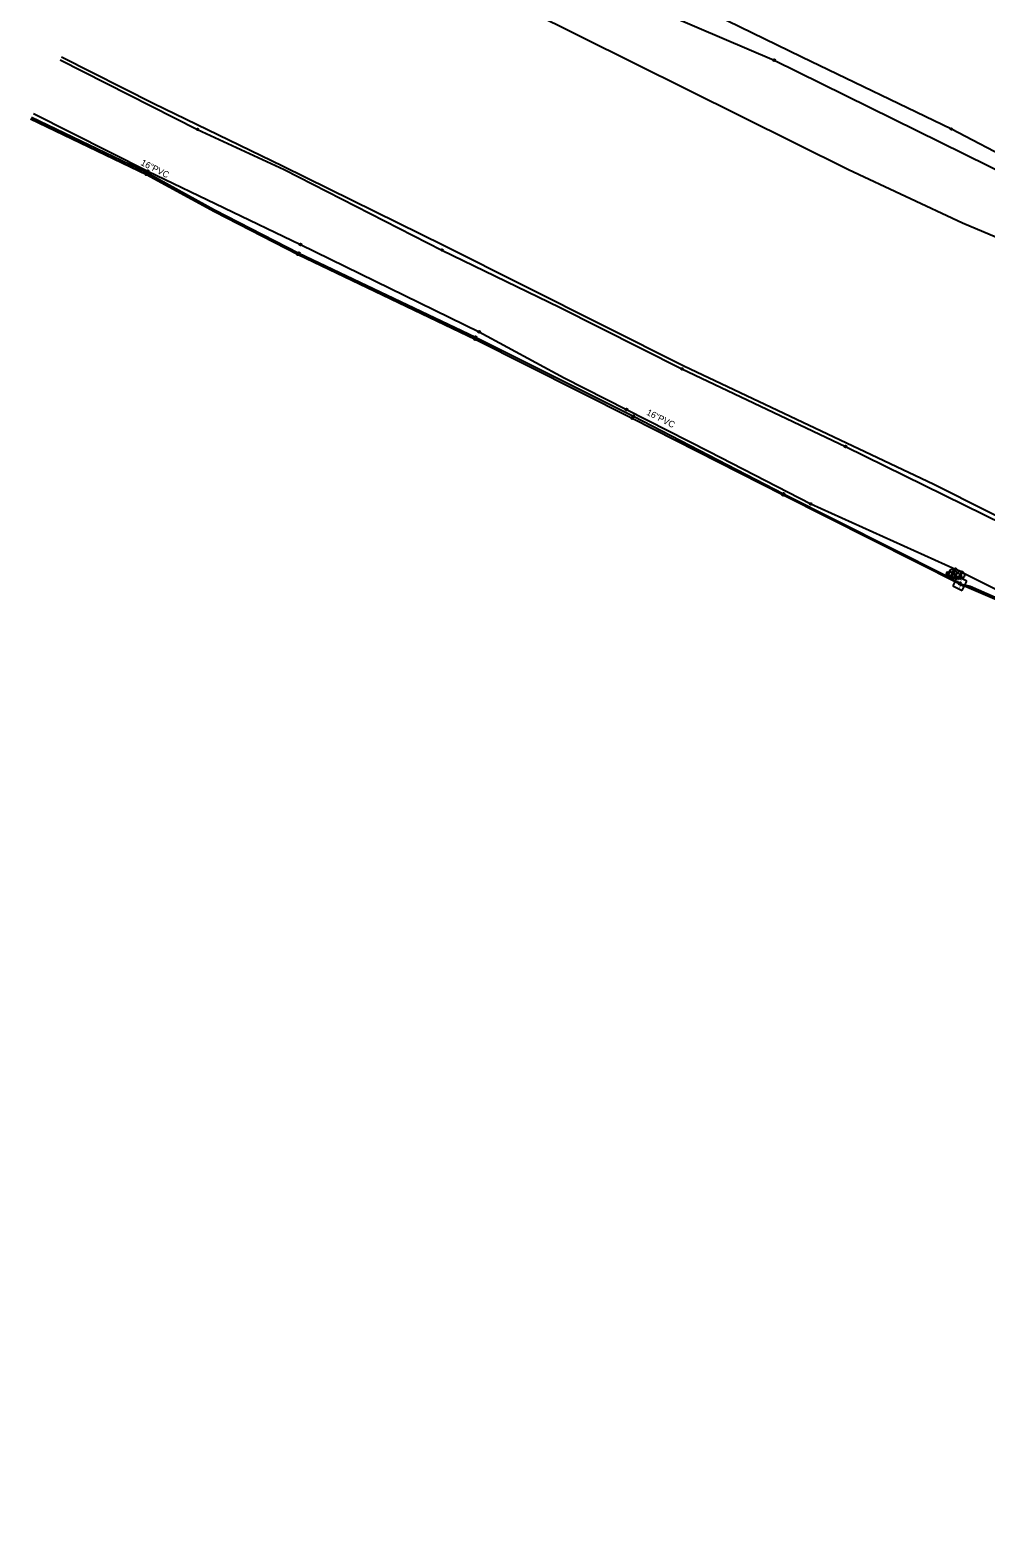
# Model space of a CAD drawing. Extents: x 2244485 to 2250986, y 199568 to 203007.
# Drawn here: x 2248328 to 2248849, y 200055 to 200876 of the extents above; entities that cross this region are included whole.
import ezdxf

# ---------------------------------------------------------------- set-up
doc = ezdxf.new("R2010")
doc.units = 0
for name, color, linetype in [('Default', 7, 'Continuous'), ('Exist Utilities Sanitary Sewer Forced Main SUE LOS B', 7, 'Continuous'), ('Exist Utilities Telephone Hand Hole CELL', 7, 'Continuous'), ('Exist Utilities Telephone UG Cable SUE LOS C', 7, 'Continuous'), ('Exist Utilities Telephone UG FO SUE LOS B', 7, 'Continuous'), ('Exist Utilities Telephone UG FO SUE LOS C', 7, 'Continuous'), ('Exist Utilities Water Fire Hydrant CELL', 7, 'Continuous'), ('Exist Utilities Water UG Line SUE LOS B', 7, 'Continuous'), ('Exist Utilities Water UG Line SUE LOS B Text', 7, 'Continuous'), ('Exist Utilities Water Valve CELL', 7, 'Continuous')]:
    doc.layers.add(name, color=color, linetype=linetype)

# ---------------------------------------------------------------- blocks, each defined once
blk = doc.blocks.new('SurveyPointCell')
at = {"layer": 'Default'}
for p, q in [((-0.5, 0), (0.5, 0)), ((0, -0.5), (0, 0.5))]:
    blk.add_line(p, q, dxfattribs=at)
blk.add_circle((0, 0), 0.5, dxfattribs=at)

msp = doc.modelspace()

# ---------------------------------------------------------------- linework, layer by layer
at = {"layer": 'Exist Utilities Sanitary Sewer Forced Main SUE LOS B'}
msp.add_lwpolyline([(2247735.41, 201350.67), (2247801.59, 201317.51), (2247922.39, 201259.82), (2248074.17, 201183.48), (2248161.38, 201141.9), (2248228.53, 201112.29), (2248334.87, 201058.12), (2248487.25, 200983.06), (2248649.22, 200895.6), (2248733.43, 200859.57), (2248875.85, 200789.39), (2249055.92, 200697.85), (2249217.76, 200621.23), (2249370.62, 200544.89)], dxfattribs=at)
at = {"layer": 'Exist Utilities Telephone Hand Hole CELL'}
for p, q in [((2248833.24, 200578.53), (2248830.61, 200573.44)), ((2248830.61, 200573.44), (2248835.7, 200570.82)), ((2248838.33, 200575.9), (2248833.24, 200578.53)), ((2248834.47, 200574.67), (2248834.47, 200574.67)), ((2248835.7, 200570.82), (2248838.33, 200575.9))]:
    msp.add_line(p, q, dxfattribs=at)
at = {"layer": 'Exist Utilities Telephone UG Cable SUE LOS C'}
msp.add_lwpolyline([(2248238.7, 201066.28), (2248423.59, 200974.24), (2248773.82, 200799.99), (2248835.88, 200770.97), (2248854.39, 200763.25), (2248860.78, 200766.45), (2248866.15, 200773.75), (2248880.19, 200799.94), (2248868.48, 200773.69), (2248865.46, 200766.31), (2248865.37, 200759.63), (2248891.36, 200747.54), (2249235.17, 200571.04), (2249362.52, 200506.1), (2249646.99, 200363.79)], dxfattribs=at)
at = {"layer": 'Exist Utilities Telephone UG FO SUE LOS B'}
for points in [[(2247734.6, 201364.13), (2247798.15, 201331.66), (2247859.88, 201301.14), (2247925.6, 201269.67), (2247988.72, 201238.28), (2248114.06, 201176.6), (2248183.16, 201141.53), (2248221.91, 201121.81), (2248290.07, 201088.12), (2248488.94, 200988.89), (2248609.32, 200928.77), (2248687.7, 200891.02), (2248748.44, 200861.37), (2248829.89, 200822.11), (2248864.68, 200804.04), (2248883.46, 200794.42), (2248944.92, 200764.27), (2249005.82, 200733.82), (2249066.5, 200704.1), (2249128.64, 200672.91), (2249190.46, 200641.51), (2249254.14, 200610.49), (2249321.49, 200578.44), (2249387.5, 200544.86)], [(2248344.53, 200859.83), (2248419.29, 200821.92), (2248466.62, 200800.01), (2248552.5, 200756.23), (2248616.5, 200725.07), (2248683.2, 200691.48), (2248772.25, 200649.25), (2248879.65, 200596.48), (2248899.78, 200585.98), (2248912.71, 200576.87), (2248936.09, 200565.52), (2248980.22, 200544.6), (2249032.26, 200518.49), (2249090.09, 200489.91), (2249149.46, 200460.97), (2249211.92, 200430.6), (2249266.25, 200404.93), (2249319.08, 200376.82), (2249375.45, 200350.06)], [(2248328.4, 200827.57), (2248391.63, 200797.41), (2248428.53, 200777.25), (2248474.15, 200753.86), (2248570.53, 200707.71), (2248656.14, 200664.65), (2248738.24, 200622.89), (2248834.42, 200574.52)], [(2248328.89, 200828.55), (2248391.84, 200798.46), (2248428.67, 200778.04), (2248474.62, 200754.59), (2248570.71, 200708.84), (2248656.71, 200665.82), (2248738.57, 200623.53), (2248826.46, 200579.25), (2248834.42, 200574.52)], [(2248834.42, 200574.52), (2248877.75, 200555.98), (2248921.13, 200534.6), (2249032.64, 200482.8), (2249142.58, 200428.84), (2249188.38, 200405.49), (2249254.87, 200369.28), (2249313.69, 200339.47), (2249478.6, 200256.38)], [(2248834.42, 200574.52), (2248840.11, 200573.18), (2248878.1, 200556.55), (2248921.45, 200535.34), (2249032.65, 200483.49), (2249143.05, 200429.5), (2249188.93, 200406.33), (2249255.33, 200370.44), (2249314.07, 200340.07), (2249478.96, 200257.14)]]:
    msp.add_lwpolyline(points, dxfattribs=at)
at = {"layer": 'Exist Utilities Telephone UG FO SUE LOS C'}
msp.add_lwpolyline([(2248345.35, 200861.45), (2248395.63, 200836.07), (2248465.71, 200802.05), (2248553.74, 200758.66), (2248684.23, 200693.17), (2248820.3, 200628.68), (2248908.04, 200584.64), (2248916.96, 200578.87), (2248981.98, 200546.97), (2249120.09, 200477.99), (2249226.44, 200426.02), (2249266.92, 200406.38), (2249295.86, 200391.44), (2249352.73, 200362.96), (2249442.05, 200319.48)], dxfattribs=at)
at = {"layer": 'Exist Utilities Water Fire Hydrant CELL'}
msp.add_line((2248830.17, 200578.94), (2248830.17, 200578.94), dxfattribs=at)
for points in [[(2248828.69, 200580.25), (2248827.53, 200580.82), (2248827.08, 200579.9), (2248828.26, 200579.32)], [(2248831.48, 200580.43), (2248832.05, 200581.58), (2248831.13, 200582.04), (2248830.56, 200580.88)], [(2248832.12, 200578.55), (2248833.27, 200577.98), (2248832.82, 200577.07), (2248831.64, 200577.65)]]:
    msp.add_lwpolyline(points, dxfattribs=at)
for radius in [1.98, 0.243]:
    msp.add_circle((2248830.17, 200578.94), radius, dxfattribs=at)
at = {"layer": 'Exist Utilities Water UG Line SUE LOS B'}
msp.add_line((2248832.07, 200582.49), (2248832.07, 200582.49), dxfattribs=at)
for points in [[(2248329.97, 200830.62), (2248392.26, 200799.22), (2248475.47, 200759.22), (2248572.73, 200711.68), (2248619.08, 200686.69), (2248652.95, 200669.4), (2248697.99, 200646.48), (2248753.28, 200617.97), (2248832.07, 200582.49)], [(2248832.07, 200582.49), (2248830.75, 200580.22), (2248830.17, 200578.94)], [(2248835.51, 200580.83), (2248832.07, 200582.49)], [(2248834.8, 200579.26), (2248835.51, 200580.83)], [(2248835.51, 200580.83), (2248922.65, 200537.42), (2249033.15, 200484.25), (2249189.81, 200407.98), (2249240.08, 200380.66), (2249481.52, 200258.57), (2249600.85, 200198.31), (2249670.02, 200162.8), (2249862.82, 200069.86), (2249895.12, 200055.15)]]:
    msp.add_lwpolyline(points, dxfattribs=at)
at = {"layer": 'Exist Utilities Water Valve CELL'}
for points in [[(2248832.2, 200581.82), (2248829.05, 200578.67), (2248830.62, 200580.24), (2248832.2, 200578.67), (2248829.05, 200581.82)], [(2248836.36, 200580.8), (2248833.21, 200577.65), (2248834.78, 200579.22), (2248836.36, 200577.65), (2248833.21, 200580.8)]]:
    msp.add_lwpolyline(points, dxfattribs=at)
for centre in [(2248830.62, 200580.24), (2248834.78, 200579.22)]:
    msp.add_circle(centre, 2.23, dxfattribs=at)

# ---------------------------------------------------------------- block references
at = {"layer": 'Default'}
for p in [(2248733.43, 200859.57), (2248419.29, 200821.92), (2248829.89, 200822.11), (2248391.63, 200797.41), (2248391.84, 200798.46), (2248392.26, 200799.22), (2248474.15, 200753.86), (2248474.62, 200754.59), (2248475.47, 200759.22), (2248552.5, 200756.23), (2248572.73, 200711.68), (2248570.53, 200707.71), (2248570.71, 200708.84), (2248683.2, 200691.48), (2248652.95, 200669.4), (2248656.14, 200664.65), (2248656.71, 200665.82), (2248772.25, 200649.25), (2248738.24, 200622.89), (2248738.57, 200623.53), (2248753.28, 200617.97), (2248830.75, 200580.22), (2248832.07, 200582.49), (2248832.07, 200582.49), (2248835.51, 200580.83), (2248835.51, 200580.83), (2248830.17, 200578.94), (2248834.42, 200574.52), (2248834.54, 200574.68), (2248834.67, 200574.71), (2248834.68, 200574.7), (2248834.8, 200579.26)]:
    msp.add_blockref('SurveyPointCell', p, dxfattribs=at)

# ---------------------------------------------------------------- texts
at = {"layer": 'Exist Utilities Telephone Hand Hole CELL'}
for p in [(2248832.35, 200575.1), (2248833.96, 200572.62)]:
    msp.add_text('H', height=2.5, rotation=332.71718, dxfattribs=at).set_placement(p)
at = {"layer": 'Exist Utilities Water UG Line SUE LOS B Text'}
for p in [(2248388.11, 200802.69), (2248663.52, 200666.69)]:
    msp.add_text('16"PVC', height=3.5, rotation=333.09153, dxfattribs=at).set_placement(p)

doc.saveas('drawing.dxf')
